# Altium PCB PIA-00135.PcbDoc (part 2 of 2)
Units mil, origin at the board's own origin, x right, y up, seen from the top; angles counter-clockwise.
Board outline 5630 x 2198.54 mil, 6 copper layers (Top Layer, Mid-Layer 1, Mid-Layer 2, Mid-Layer 3, Mid-Layer 4, Bottom Layer), stack 61.94 mil thick; 90 components, 35 nets, 210 pads, 457 vias.
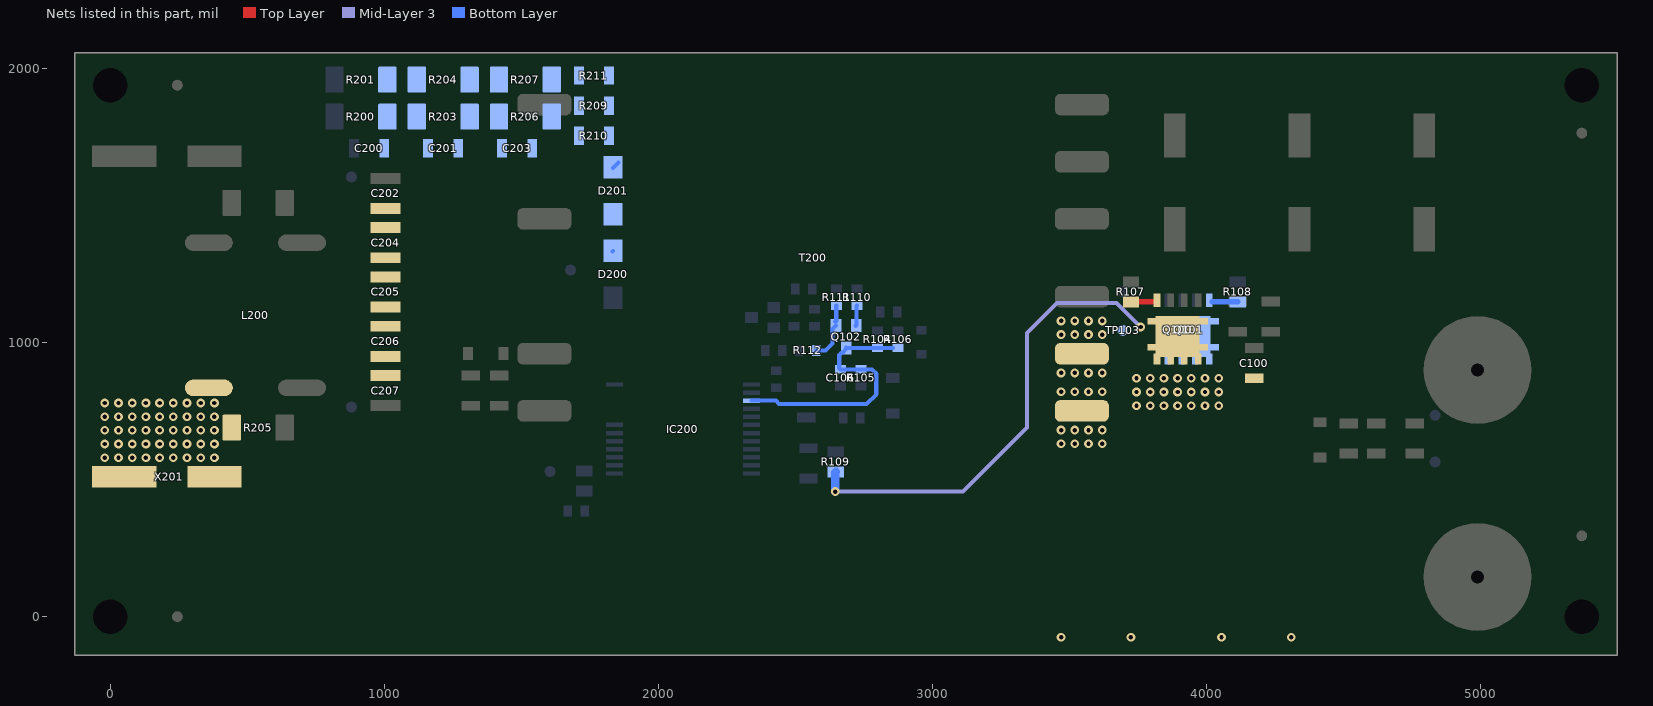
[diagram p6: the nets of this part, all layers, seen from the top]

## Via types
v1: diameter 32, hole 16, Top Layer to Bottom Layer, tented both sides, 409 vias
v2: diameter 32, hole 16, Top Layer to Bottom Layer, tented bottom, 48 vias

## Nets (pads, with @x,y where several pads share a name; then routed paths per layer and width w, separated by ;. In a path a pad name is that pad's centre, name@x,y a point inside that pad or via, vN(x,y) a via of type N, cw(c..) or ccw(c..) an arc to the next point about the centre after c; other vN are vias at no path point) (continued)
NetL200_3: L200.3 R205.1 X201.1 X201.2
  other v1: -20,580.08 30,580.08 80,580.08 130,580.08 180,580.08 230,580.08 280,580.08 330,580.08 380,580.08 -20,630.08 30,630.08 80,630.08 130,630.08 180,630.08 230,630.08 280,630.08 330,630.08 380,630.08 -20,680.08 30,680.08 80,680.08 130,680.08 180,680.08 230,680.08 280,680.08 330,680.08 380,680.08 -20,730.08 30,730.08 80,730.08 130,730.08 180,730.08 230,730.08 280,730.08 330,730.08 380,730.08 -20,780.08 30,780.08 80,780.08 130,780.08 180,780.08 230,780.08 280,780.08 330,780.08 380,780.08
NetQ100_G: Q100.G R107.1 | length 99.9
  Top Layer w20: R107.1@3725,1149 3817.99,1149 3820,1151 Q100.G@3820,1155.11
NetQ101_G: Q101.G R108.1 | length 93
  Bottom Layer w20: 4022,1149 R108.1@4115,1149
NetQ102_B: Q102.B R111.2 R112.1 | length 203
  Bottom Layer w15: R112.1@2576.5,971.69 2610.5,971.69 2636.41,997.6 2636.41,1050.6 Q102.B@2648.5,1062.69 ; Q102.B@2645.5,1076.69 2647.5,1076.69 2649.5,1078.69 2649.5,1134.69 R111.2@2650.5,1135.69
NetQ102_E: Q102.E R110.2 | length 76.1
  Bottom Layer w15: Q102.E@2720.5,1061.69 2724,1065.19 2724,1134.19 R110.2@2725.5,1135.69
SR-K: C100.1 Q100.D Q101.D R109.1 T200.7 T200.8 TP103.1 | length 1711.2
  Mid-Layer 3 w15: v1(2645.5,456.69) 3111.69,456.69 3345,690 3345,1035 3455,1145 3672.15,1145 v1(3760,1057.15)
  Bottom Layer w30: v1(2645.5,456.69) 2645.5,526.05 R109.1@2648.14,528.69
  other v1: 3470,-75 3724.6,-75 4055.39,-75 4310,-75 3470,630.94 3520,630.94 3570,630.94 3620,630.94 3470,680.94 3520,680.94 3570,680.94 3620,680.94 3745,770 3795,770 3845,770 3895,770 3945,770 3995,770 4045,770 3745,820 3795,820 3845,820 3895,820 3945,820 3995,820 4045,820 3470,820.94 3520,820.94 3570,820.94 3620,820.94 3745,870 3795,870 3845,870 3895,870 3945,870 3995,870 4045,870 3470,889.6 3520,889.6 3570,889.6 3620,889.6 3470,1029.6 3520,1029.6 3570,1029.6 3620,1029.6 3470,1079.6 3520,1079.6 3570,1079.6 3620,1079.6
Vbus1: C206.2 C207.1
Vbus2: C205.2 C206.1
Vbus3: C204.2 C205.1
Vbus4: C202.2 C204.1
VFB: C106.2 IC200.3 Q102.C R104.1 R105.2 R106.1 | length 938.1
  Bottom Layer w15: IC200.3@2340.5,788.34 2428.84,788.34 2440.5,776.69 2760.5,776.69 2795.5,811.69 2795.5,886.69 2780.5,901.69 R105.2@2745.5,901.69 ; C106.2@2660.5,906.69 2660.5,955.69 2669.5,964.69 2673.5,964.69 2685.5,976.69 Q102.C@2685.5,980.69 ; C106.2@2665.5,902.69 2739.5,902.69 R105.2@2740.5,901.69 ; Q102.C@2685.5,981.69 2686.5,980.69 R104.1@2800.5,980.69 R106.1@2855.5,980.69
Vsnub1: C200.2 C201.1 R200.2 R201.2 R203.1 R204.1
Vsnub2: C201.2 C203.1 R203.2 R204.2 R206.1 R207.1
Vsnub3: C203.2 R206.2 R207.2 R209.1 R210.1 R211.1
Vsnub4: D201.K R209.2 R210.2 R211.2 | length 28.3
  Bottom Layer w15: D201.K@1835,1637 D201.K@1855,1657
Vsnub5: D200.K D201.A | length 2.9
  Bottom Layer w15: D200.K@1832.96,1333 D200.K@1835,1335.04
pads on no net: HOLE1.0 HOLE2.0 HOLE3.0 HOLE4.0 IC200.8 IC200.9 IC200.10 IC200.11 IC200.12 IC200.15 PM1.0 PM2.0 PM3.0 PM4.0 PM5.0 PM6.0 PM7.0 PM8.0 TP100.2 TP103.2 TP104.2 TP105.2 TP200.2 TP201.2 TP202.2 TP203.2

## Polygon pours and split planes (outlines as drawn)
NetL200_3 on Top Layer "NETL200_3_L01_P449" (solid, remove dead copper, pour order 449): -60,455.08 465,455.08 480,470.08 480,855.08 465,870.08 -60,870.08 -75,855.08 -75,470.08
NetL200_2 on Top Layer "NETL200_2_L01_P448" (solid, remove dead copper, pour order 448): -60,1745 465,1745 480,1730 480,1345 465,1330 -60,1330 -75,1345 -75,1730
"13.5 V (RTN)" on Top Layer "NONET_L01_P-001" (solid, pour order 382): 4700,-100 4385,-100 4370,-85 4370,600 4385,615 4700,615 5190,615 5205,600 5205,-85 5190,-100
NetC100_2 on Top Layer "NETC100_2_L01_P001" (solid, pour order 1): 4285,1015 4285,1095 4275,1105 4075,1105 4065,1095 4065,1015 4120,960 4230,960
SR-K on Top Layer "NONET_L01_P-001" (solid, pour order 441): 3445,1095 3455,1105 4040,1105 4050,1095 4050,1010 4115,945 4235,945 4300,1010 4300,1095 4310,1105 4335,1105 4345,1095 4345,-85 4330,-100 3460,-100 3445,-85
NetC102_2 on Top Layer "NETC102_2_L01_P104" (solid, pour order 104): 4665,700 4650,685 4385,685 4370,700 4370,1100 4345,1125 3855,1125 3845,1135 3845,1190 3840,1195 3825,1195 3820,1200 3820,1245 3810,1255 3685,1255 3675,1245 3675,1135 3665,1125 3454.93,1125 3444.83,1135.1 3444.83,1484.81 3455.02,1495 4845,1495 4885,1455 4885,1255 4885,1140 4665,920
IC200A_D on Top Layer "NONET_L01_P-001" (solid, pour order 428): 1670,1350 1682.73,1362.73 1682.73,1479.57 1671.2,1491.1 1440,1491.1 1430,1481.1 1430,1480 1430,1365 1445,1350
"HV+ (900 V)" on Top Layer "NONET_L01_P-001" (solid, pour order 421): 610,1330 785,1330 800,1345 800,1490 890,1580 1054.14,1580 1095,1620.85 1095,1655 1110,1670 1585,1670 1682.73,1767.73 1682.73,1987.27 1660,2010 675,2010 600,1935 600,1340
"13.5 V (+)" on Top Layer "Top Layer-13.5 V (+)" (solid, pour order 163): 5190,685 5205,700 5205,2000 5190,2015 3455,2015 3445,2005 3445,1525 3455,1515 4860,1515 4905,1470 4905,1125 4685,905 4685,700 4700,685
"HV RTN" on Top Layer "HV_RTN_L01_P381" (solid, pour order 381): 615,870 800,870 880,790 950,790 1220,790 1230,780 1230,710 1240,700 1780,700 1871.1,608.9 1871.1,589.73 1871.1,589.72 1871.1,-88.9 1860,-100 675,-100 600,-25.01 600,855
Vbus3 on Top Layer "VBUS3_L01_P012" (solid, pour order 12): 1060,1310 1060,1240 950,1240 950,1310
Vbus4 on Top Layer "VBUS4_L01_P011" (solid, pour order 11): 1060,1490 1060,1420 950,1420 950,1490
Vbus2 on Top Layer "VBUS2_L01_P013" (solid, pour order 13): 1060,1130 1060,1060 950,1060 950,1130
Vbus1 on Top Layer "VBUS1_L01_P014" (solid, pour order 14): 1060,950 1060,880 950,880 950,950
NetL200_3 on Bottom Layer "NETL200_3_L06_P459" (solid, remove dead copper, pour order 459): -60,455.08 465,455.08 480,470.08 480,855.08 465,870.08 -60,870.08 -75,855.08 -75,470.08
NetL200_2 on Bottom Layer "NETL200_2_L06_P458" (solid, remove dead copper, pour order 458): -60,1745 465,1745 480,1730 480,1345 465,1330 -60,1330 -75,1345 -75,1730
"13.5 V (RTN)" on Bottom Layer "NONET_L01_P-001" (solid, pour order 443): 4700,-100 4385,-100 4370,-85 4370,600 4385,615 4700,615 5190,615 5205,600 5205,-85 5190,-100
SR-K on Bottom Layer "NONET_L01_P-001" (solid, pour order 442): 3445,1095 3455,1105 4040,1105 4050,1095 4050,1010 4115,945 4235,945 4300,1010 4300,1095 4310,1105 4335,1105 4345,1095 4345,-85 4330,-100 3460,-100 3445,-85
NetC102_2 on Bottom Layer "NETC102_2_L06_P383" (solid, pour order 383): 4665,700 4650,685 4385,685 4370,700 4370,1100 4345,1125 4175,1125 4165,1135 4165,1245 4155,1255 4035,1255 4025,1245 4025,1200 4020,1195 3990,1195 3985,1190 3985,1135 3975,1125 3454.93,1125 3444.83,1135.1 3444.83,1484.81 3455.02,1495 4845,1495 4885,1455 4885,1255 4885,1140 4665,920
NetC100_2 on Bottom Layer "NETC100_2_L06_P437" (solid, pour order 437): 4285,1015 4285,1095 4275,1105 4075,1105 4065,1095 4065,1015 4120,960 4230,960
"13.5 V (+)" on Bottom Layer "Top Layer-13.5 V (+)" (solid, pour order 404): 5190,685 5205,700 5205,2000 5190,2015 3455,2015 3445,2005 3445,1525 3455,1515 4860,1515 4905,1470 4905,1125 4685,905 4685,700 4700,685
Vsnub4 on Bottom Layer "NONET_L01_P-001" (solid, pour order 370): 1802,2010 1870,2010 1870,1718.5 1870,1600 1800,1600 1800,1682 1800,1693.91 1802,1695.91
"HV+ (900 V)" on Bottom Layer "NONET_L01_P-001" (solid, pour order 375): 600,1935 600,1340 610,1330 785,1330 800,1345 800,1490 890,1580 908,1598 908,1743.5 872,1743.5 852,1763.49 852,2005.28 847.29,2010 675,2010
Vsnub1 on Bottom Layer "NONET_L01_P-001" (solid, pour order 374): 1178,1675 1173,1670 987,1670 982,1675 982,1743.5 977.99,1747.5 977.99,2005.28 982.7,2010 1147.29,2010 1152,2005.28 1152,1769.49 1178,1743.5
Vsnub2 on Bottom Layer "NONET_L01_P-001" (solid, pour order 373): 1252,1675 1257,1670 1443,1670 1448,1675 1448,1743.5 1452,1747.5 1452,2005.28 1447.29,2010 1282.7,2010 1277.99,2005.28 1277.99,1769.49 1252,1743.5
Vsnub3 on Bottom Layer "NONET_L01_P-001" (solid, pour order 371): 1728,2010 1582.7,2010 1577.99,2005.28 1577.99,1757.99 1563.5,1743.5 1522,1743.5 1522,1670 1675,1670 1728,1723 1728,1788.5
Vsnub5 on Bottom Layer "NONET_L01_P-001" (solid, pour order 369): 1800,1510 1870,1510 1870,1295 1800,1295
IC200A_D on Bottom Layer "NONET_L01_P-001" (solid, pour order 363): 1870.6,839.33 1808.39,839.33 1808.39,1041.6 1645,1205 1645,1325 1620,1350 1445,1350 1430,1365 1430,1481.1 1440,1491.1 1671.2,1491.1 1730,1432.3 1730,1245 1770,1205 1870.6,1205
"HV RTN" on Bottom Layer "HV_RTN_L06_P146" (solid, pour order 146): 880,790 800,870 615,870 600,855 600,-25 660,-85 675,-100 1860,-100 1871.1,-88.9 1871.1,530.67 1808.39,530.67 1808.39,494.59 1808.39,368.39 1730,290 1650,290 1630,310 1630,445 1686.69,501.69 1756.69,501.69 1770.5,515.5 1770.5,571.69 1798.8,600 1871.1,600 1871.1,711.09 1852.19,730 1732.19,730 1685.5,776.69 1685.5,989.5 1575,1100 1255,1100 1195,1100 1127.5,1032.5 1127.5,827.5 1090,790
NetC102_2 on Bottom Layer "NETC102_2_L06_P159" (solid, remove dead copper, pour order 159): 2500.5,816.69 2500.5,891.69 2510.5,901.69 2610.5,901.69 2620.5,891.69 2620.5,816.69 2610.5,806.69 2510.5,806.69
NetL200_3 on Mid-Layer 1 "NETL200_3_L02_P451" (solid, remove dead copper, pour order 451): -60,455.08 465,455.08 480,470.08 480,855.08 465,870.08 -60,870.08 -75,855.08 -75,470.08
NetL200_2 on Mid-Layer 1 "NETL200_2_L02_P450" (solid, remove dead copper, pour order 450): -60,1745 465,1745 480,1730 480,1345 465,1330 -60,1330 -75,1345 -75,1730
"13.5 V (RTN)" on Mid-Layer 1 "NONET_L01_P-001" (solid, pour order 447): 4700,-100 4385,-100 4370,-85 4370,600 4385,615 4700,615 5190,615 5205,600 5205,-85 5190,-100
SR-K on Mid-Layer 1 "NONET_L01_P-001" (solid, pour order 432): 3445,1095 3455,1105 4040,1105 4050,1095 4050,1010 4115,945 4235,945 4300,1010 4300,1095 4310,1105 4335,1105 4345,1095 4345,-85 4330,-100 3460,-100 3445,-85
NetC100_2 on Mid-Layer 1 "NETC100_2_L02_P433" (solid, pour order 433): 4285,1015 4285,1095 4275,1105 4075,1105 4065,1095 4065,1015 4120,960 4230,960
IC200A_D on Mid-Layer 1 "NONET_L01_P-001" (solid, pour order 424): 1670,1350 1682.73,1362.73 1682.73,1479.57 1671.2,1491.1 1440,1491.1 1430,1481.1 1430,1480 1430,1365 1445,1350
"HV+ (900 V)" on Mid-Layer 1 "NONET_L01_P-001" (solid, pour order 376): 890,1580 800,1490 800,1345 785,1330 610,1330 600,1340 600,1935 675,2010 1660,2010 1682.73,1987.27 1682.73,1767.73 1585,1670 1110,1670 1095,1655 1095,1620.85 1054.14,1580
"HV RTN" on Mid-Layer 1 "HV_RTN_L02_P420" (solid, pour order 420): 880,790 800,870 615,870 600,855 600,-25 660,-85 675,-100 1860,-100 1871.1,-88.9 1871.1,711.09 1852.19,730 1732.19,730 1685.5,776.69 1685.5,989.5 1575,1100 1255,1100 1195,1100 1127.5,1032.5 1127.5,827.5 1090,790
"13.5 V (+)" on Mid-Layer 1 "Top Layer-13.5 V (+)" (solid, pour order 408): 5190,685 5205,700 5205,2000 5190,2015 3455,2015 3445,2005 3445,1525 3455,1515 4860,1515 4905,1470 4905,1125 4685,905 4685,700 4700,685
NetC102_2 on Mid-Layer 1 "NETC102_2_L02_P389" (solid, pour order 389): 4665,700 4650,685 4385,685 4370,700 4370,1100 4345,1125 3454.93,1125 3425,1095.07 3425,415 3410,400 2325,400 2310,415 2310,1480 2325,1495 4845,1495 4885,1455 4885,1255 4885,1140 4665,920
"HV+ (900 V)" on Mid-Layer 3 "NONET_L01_P-001" (solid, pour order 461): 890,1580 800,1490 800,1345 785,1330 610,1330 600,1340 600,1935 675,2010 1660,2010 1682.73,1987.27 1682.73,1767.73 1585,1670 1110,1670 1095,1655 1095,1620.85 1054.14,1580
NetL200_3 on Mid-Layer 3 "NETL200_3_L04_P455" (solid, remove dead copper, pour order 455): -60,455.08 465,455.08 480,470.08 480,855.08 465,870.08 -60,870.08 -75,855.08 -75,470.08
NetL200_2 on Mid-Layer 3 "NETL200_2_L04_P454" (solid, remove dead copper, pour order 454): -60,1745 465,1745 480,1730 480,1345 465,1330 -60,1330 -75,1345 -75,1730
"13.5 V (RTN)" on Mid-Layer 3 "NONET_L01_P-001" (solid, pour order 445): 4700,-100 4385,-100 4370,-85 4370,600 4385,615 4700,615 5190,615 5205,600 5205,-85 5190,-100
SR-K on Mid-Layer 3 "NONET_L01_P-001" (solid, pour order 438): 3445,1095 3455,1105 4040,1105 4050,1095 4050,1010 4115,945 4235,945 4300,1010 4300,1095 4310,1105 4335,1105 4345,1095 4345,-85 4330,-100 3460,-100 3445,-85
NetC100_2 on Mid-Layer 3 "NETC100_2_L04_P435" (solid, pour order 435): 4285,1015 4285,1095 4275,1105 4075,1105 4065,1095 4065,1015 4120,960 4230,960
IC200A_D on Mid-Layer 3 "NONET_L01_P-001" (solid, pour order 429): 1670,1350 1682.73,1362.73 1682.73,1479.57 1671.2,1491.1 1440,1491.1 1430,1481.1 1430,1480 1430,1365 1445,1350
"HV RTN" on Mid-Layer 3 "HV_RTN_L04_P418" (solid, pour order 418): 880,790 800,870 615,870 600,855 600,-25 660,-85 675,-100 1860,-100 1871.1,-88.9 1871.1,711.09 1852.19,730 1732.19,730 1685.5,776.69 1685.5,989.5 1575,1100 1255,1100 1195,1100 1127.5,1032.5 1127.5,827.5 1090,790
"13.5 V (+)" on Mid-Layer 3 "Top Layer-13.5 V (+)" (solid, pour order 406): 5190,685 5205,700 5205,2000 5190,2015 3455,2015 3445,2005 3445,1525 3455,1515 4860,1515 4905,1470 4905,1125 4685,905 4685,700 4700,685
NetC102_2 on Mid-Layer 3 "NETC102_2_L04_P386" (solid, pour order 386): 4665,700 4650,685 4385,685 4370,700 4370,1100 4345,1125 3454.93,1125 3425,1095.07 3425,415 3410,400 2325,400 2310,415 2310,1480 2325,1495 4845,1495 4885,1455 4885,1255 4885,1140 4665,920
"HV+ (900 V)" on Mid-Layer 2 "NONET_L01_P-001" (solid, pour order 460): 890,1580 800,1490 800,1345 785,1330 610,1330 600,1340 600,1935 675,2010 1660,2010 1682.73,1987.27 1682.73,1767.73 1585,1670 1110,1670 1095,1655 1095,1620.85 1054.14,1580
NetL200_3 on Mid-Layer 2 "NETL200_3_L03_P453" (solid, remove dead copper, pour order 453): -60,455.08 465,455.08 480,470.08 480,855.08 465,870.08 -60,870.08 -75,855.08 -75,470.08
NetL200_2 on Mid-Layer 2 "NETL200_2_L03_P452" (solid, remove dead copper, pour order 452): -60,1745 465,1745 480,1730 480,1345 465,1330 -60,1330 -75,1345 -75,1730
"13.5 V (RTN)" on Mid-Layer 2 "NONET_L01_P-001" (solid, pour order 446): 4700,-100 4385,-100 4370,-85 4370,600 4385,615 4700,615 5190,615 5205,600 5205,-85 5190,-100
SR-K on Mid-Layer 2 "NONET_L01_P-001" (solid, pour order 439): 3445,1095 3455,1105 4040,1105 4050,1095 4050,1010 4115,945 4235,945 4300,1010 4300,1095 4310,1105 4335,1105 4345,1095 4345,-85 4330,-100 3460,-100 3445,-85
NetC100_2 on Mid-Layer 2 "NETC100_2_L03_P434" (solid, pour order 434): 4285,1015 4285,1095 4275,1105 4075,1105 4065,1095 4065,1015 4120,960 4230,960
IC200A_D on Mid-Layer 2 "NONET_L01_P-001" (solid, pour order 366): 1670,1350 1682.73,1362.73 1682.73,1479.57 1671.2,1491.1 1440,1491.1 1430,1481.1 1430,1480 1430,1365 1445,1350
"HV RTN" on Mid-Layer 2 "HV_RTN_L03_P419" (solid, pour order 419): 880,790 800,870 615,870 600,855 600,-25 660,-85 675,-100 1860,-100 1871.1,-88.9 1871.1,711.09 1852.19,730 1732.19,730 1685.5,776.69 1685.5,989.5 1575,1100 1255,1100 1195,1100 1127.5,1032.5 1127.5,827.5 1090,790
"13.5 V (+)" on Mid-Layer 2 "Top Layer-13.5 V (+)" (solid, pour order 407): 5190,685 5205,700 5205,2000 5190,2015 3455,2015 3445,2005 3445,1525 3455,1515 4860,1515 4905,1470 4905,1125 4685,905 4685,700 4700,685
NetC102_2 on Mid-Layer 2 "NETC102_2_L03_P388" (solid, pour order 388): 4665,700 4650,685 4385,685 4370,700 4370,1100 4345,1125 3454.93,1125 3425,1095.07 3425,415 3410,400 2325,400 2310,415 2310,1480 2325,1495 4845,1495 4885,1455 4885,1255 4885,1140 4665,920
NetL200_3 on Mid-Layer 4 "NETL200_3_L05_P457" (solid, remove dead copper, pour order 457): -60,455.08 465,455.08 480,470.08 480,855.08 465,870.08 -60,870.08 -75,855.08 -75,470.08
NetL200_2 on Mid-Layer 4 "NETL200_2_L05_P456" (solid, remove dead copper, pour order 456): -60,1745 465,1745 480,1730 480,1345 465,1330 -60,1330 -75,1345 -75,1730
"13.5 V (RTN)" on Mid-Layer 4 "NONET_L01_P-001" (solid, pour order 444): 4700,-100 4385,-100 4370,-85 4370,600 4385,615 4700,615 5190,615 5205,600 5205,-85 5190,-100
SR-K on Mid-Layer 4 "NONET_L01_P-001" (solid, pour order 440): 3445,1095 3455,1105 4040,1105 4050,1095 4050,1010 4115,945 4235,945 4300,1010 4300,1095 4310,1105 4335,1105 4345,1095 4345,-85 4330,-100 3460,-100 3445,-85
NetC100_2 on Mid-Layer 4 "NETC100_2_L05_P436" (solid, pour order 436): 4285,1015.08 4285,1095 4275,1105 4074.91,1105 4065.25,1095.34 4065.25,1015.34 4120.25,960.34 4230.25,960.34
IC200A_D on Mid-Layer 4 "NONET_L01_P-001" (solid, pour order 430): 1670,1350 1682.73,1362.73 1682.73,1479.57 1671.2,1491.1 1440,1491.1 1430,1481.1 1430,1480 1430,1365 1445,1350
"HV RTN" on Mid-Layer 4 "HV_RTN_L05_P417" (solid, pour order 417): 880,790 800,870 615,870 600,855 600,-25 660,-85 675,-100 1860,-100 1871.1,-88.9 1871.1,711.09 1852.19,730 1732.19,730 1685.5,776.69 1685.5,989.5 1575,1100 1255,1100 1195,1100 1127.5,1032.5 1127.5,827.5 1090,790
"13.5 V (+)" on Mid-Layer 4 "Top Layer-13.5 V (+)" (solid, pour order 405): 5190,685 5205,700 5205,2000 5190,2015 3455,2015 3445,2005 3445,1525 3455,1515 4860,1515 4905,1470 4905,1125 4685,905 4685,700 4700,685
NetC102_2 on Mid-Layer 4 "NETC102_2_L05_P387" (solid, pour order 387): 4665,700 4650,685 4385,685 4370,700 4370,1100 4345,1125 3454.93,1125 3425,1095.07 3425,415 3410,400 2325,400 2310,415 2310,1480 2325,1495 4845,1495 4885,1455 4885,1255 4885,1140 4665,920

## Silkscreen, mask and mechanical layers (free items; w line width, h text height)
Top Overlay:
  drawing of 30 lines, arcs and shapes, not listed
  text "VIN (+)" at 115,1816.69 h100
  text "900V" at -15,960 h118.11
  text "⊕" at 4600,783.52 h400
  text "13.5V / 6.37A" at 4695,473.08 h100
  text "86W" at 4865,386.27 h100
  text "VIN (-)" at 115,316.69 h100
  text "'.ProductNamePCB'" at 880,205 h118.11
  text "HV" at 1704.68,134.68 h78.74
  text "LV" at 2329.68,134.68 h78.74
  text "'.PCBNumber'" at 910,120 h100
  text "⊖" at 4600,38.52 h400
Bottom Solder:
  lines w10: 2809.41,83.78 2809.41,44.41 2848.78,44.41 ; 2809.41,280.63 2809.41,320 2848.78,320 ; 3175.63,44.41 3215,44.41 3215,83.78 ; 3175.63,320 3215,320 3215,280.63
Remark:
  text "Product:" at 599.72,-439.35 h70
  text ".TitleP" at 845,-440 h70
  text ".DATE_PRINT" at 595.09,-565.76 h70
  text ".TIME_PRINT" at 945.09,-565.76 h70
  text ".Pcb_File_Name_No_Path" at 595.09,-665.76 h70
  text ".Printout_Name" at 595.09,-765.76 h70
  text ".PLOT_FILE_NAME" at 595.09,-865.76 h70
  text ".PRINT_SCALE" at 595.09,-965.76 h70
  text "Attention: The wires of THT components must not stand out more than 1.0mm !!" at 595.09,-1065.76 h70
Outline:
  the board outline again, w10
Cutout:
  lines w10: -135,-140 ccw(c-130,-140) -130,-145 ; -135,-140 ccw(c-130,-140) -130,-145 ; -135,-140 -135,2058.54 ; -135,2058.54 cw(c-130,2058.54) -130,2063.54 ; -135,2058.54 cw(c-130,2058.54) -130,2063.54 ; -130,-145 5500,-145 ; -130,2063.54 5500,2063.54 ; 1348.32,1519.55 ccw(c1344.8,1523.11) 1348.34,1519.57 ; 1348.32,1519.55 ccw(c1344.8,1523.11) 1348.34,1519.57 ; 1348.32,1519.55 ccw(c1358.96,1508.96) 1343.94,1508.96 1343.94,1325 ccw(c1358.96,1325) 1373.97,1325 1373.97,1500.67 ; 1348.33,1519.57 ccw(c1358.96,1508.96) 1348.32,1519.55 ; 1348.34,1519.57 ccw(c1358.96,1508.96) 1348.33,1519.57 ; 1348.34,1519.58 ccw(c1358.96,1508.96) 1348.34,1519.57 ; 1348.34,1519.58 cw(c1358.96,1508.96) 1348.37,1519.6 ; 1348.34,1519.58 1348.39,1519.62 ; 1348.34,1519.57 1348.34,1519.58 ; 1348.33,1519.57 1348.34,1519.57 ; 1348.34,1519.57 1348.37,1519.61 ; 1348.37,1519.61 ccw(c1344.84,1523.14) 1348.39,1519.62 ; 1348.37,1519.6 ccw(c1344.84,1523.14) 1348.37,1519.61 ; 1348.37,1519.61 ccw(c1344.84,1523.14) 1348.39,1519.62 ; 1348.39,1519.62 1399.33,1570.56 ; 1360,1175.01 ccw(c1360,1180.01) 1360.04,1175.01 ; 1360,1175.01 ccw(c1360,1160) 1360,1144.98 1596.71,1144.98 ; 1360,1175.01 1360.04,1175.01 ; 1360.04,1175.01 1604.97,1175.01 ; 1373.97,1500.67 cw(c1378.97,1500.67) 1375.45,1504.22 ; 1373.97,1500.67 cw(c1378.97,1500.67) 1375.43,1504.2 ; 1375.45,1504.22 1414.73,1543.5 ; 1375.43,1504.2 1375.45,1504.22 ; 1399.35,1570.59 cw(c1410,1560) 1399.38,1570.61 ; 1399.33,1570.56 ccw(c1395.81,1574.11) 1399.35,1570.58 ; 1399.35,1570.58 ccw(c1395.81,1574.11) 1399.35,1570.59 ; 1399.33,1570.56 ccw(c1395.81,1574.11) 1399.35,1570.58 ; 1399.35,1570.58 1399.38,1570.61 ; 1399.33,1570.56 1399.38,1570.61 ; 1399.38,1570.61 ccw(c1410,1560) 1399.38,1570.61 ; 1399.39,1570.62 ccw(c1410,1560) 1399.38,1570.61 ; 1399.4,1570.63 ccw(c1410,1560) 1399.39,1570.62 ; 1399.4,1570.63 cw(c1410,1560) 1410,1575.01 1710,1575.01 cw(c1710,1560) 1725.01,1560 cw(c1710,1560) 1710,1544.98 1418.29,1544.98 ; 1399.38,1570.61 ccw(c1395.84,1574.15) 1399.4,1570.63 ; 1399.38,1570.61 ccw(c1395.84,1574.15) 1399.4,1570.63 ; 1399.38,1570.61 1399.39,1570.62 ; 1399.38,1570.61 1399.38,1570.61 ; 1414.75,1543.52 cw(c1418.29,1539.98) 1418.29,1544.98 ; 1414.73,1543.5 cw(c1418.29,1539.98) 1418.29,1544.98 ; 1414.73,1543.5 1414.75,1543.52 ; 1596.71,1144.98 cw(c1596.71,1139.98) 1600.26,1143.5 ; 1596.71,1144.98 cw(c1596.71,1139.98) 1600.24,1143.52 1600.26,1143.5 ; 1600.26,1143.5 1728.5,1015.26 ; 1604.96,1175.01 ccw(c1605,1180.01) 1605,1175.01 ; 1605,1175.01 cw(c1605,1160) 1615.61,1170.61 ; 1604.97,1175.01 1605,1175.01 ; 1615.65,1170.58 ccw(c1619.18,1174.11) 1615.66,1170.56 ; 1615.64,1170.59 ccw(c1605,1160) 1615.61,1170.61 ; 1615.65,1170.58 ccw(c1619.18,1174.11) 1615.68,1170.55 ; 1615.64,1170.59 ccw(c1619.18,1174.11) 1615.65,1170.58 ; 1615.65,1170.58 1615.61,1170.61 ; 1615.61,1170.61 ccw(c1619.15,1174.15) 1615.61,1170.61 ; 1615.61,1170.61 ccw(c1619.15,1174.15) 1615.61,1170.61 ; 1615.61,1170.61 ccw(c1605,1160) 1615.61,1170.61 ; 1615.61,1170.61 1615.66,1170.56 ; 1615.66,1170.56 1615.68,1170.55 ; 1615.68,1170.55 1755.55,1030.68 ; 1728.5,1015.26 cw(c1724.98,1011.71) 1729.98,1011.71 ; 1728.5,1015.26 1728.52,1015.24 cw(c1724.98,1011.71) 1729.98,1011.71 ; 1729.98,810 ccw(c1745,810) 1734.36,799.4 ; 1729.98,810 1729.98,1011.71 ; 1729.98,810 1729.98,810 ; 1734.4,799.36 ccw(c1745,810) 1734.41,799.35 ; 1734.38,799.38 ccw(c1745,810) 1734.4,799.36 ; 1734.38,799.38 cw(c1745,810) 1734.36,799.4 ; 1734.41,799.35 cw(c1730.88,795.81) 1734.41,799.35 ; 1734.38,799.38 ccw(c1730.84,795.84) 1734.36,799.4 ; 1734.38,799.38 ccw(c1730.84,795.84) 1734.36,799.4 ; 1734.38,799.38 1734.41,799.35 ; 1734.38,799.38 1734.4,799.36 ; 1734.4,799.36 1734.43,799.33 ; 1734.43,799.33 ccw(c1730.88,795.81) 1734.41,799.35 ; 1734.43,799.33 ccw(c1730.88,795.81) 1734.41,799.35 ; 1734.43,799.33 1764.33,769.43 ; 1755.55,1030.68 ccw(c1759.11,1034.18) 1755.58,1030.65 ; 1755.55,1030.68 1755.56,1030.66 ; 1755.56,1030.66 ccw(c1759.11,1034.18) 1755.58,1030.65 ; 1755.58,1030.65 ccw(c1759.11,1034.18) 1755.59,1030.64 cw(c1745,1020) 1755.61,1030.61 ; 1755.58,1030.65 1755.61,1030.61 ; 1755.56,1030.66 1755.61,1030.61 ; 1755.61,1030.61 ccw(c1759.15,1034.15) 1755.61,1030.61 ; 1755.61,1030.61 ccw(c1759.15,1034.15) 1755.61,1030.61 ; 1755.61,1030.61 ccw(c1745,1020) 1755.61,1030.61 ; 1755.61,1030.61 cw(c1745,1020) 1760.01,1020 ; 1760.01,818.29 ccw(c1765.01,818.29) 1761.49,814.73 ; 1760.01,818.29 ccw(c1765.01,818.29) 1761.48,814.75 1761.49,814.73 ; 1760.01,818.29 1760.01,1019.97 ; 1760.01,1019.96 cw(c1765.01,1020) 1760.01,1020 ; 1760.01,1019.97 1760.01,1020 ; 1760.01,1020 ccw(c1745,1020) 1760.01,1020 ; 1761.49,814.73 1779.73,796.49 ; 1764.35,769.41 ccw(c1760.81,765.88) 1764.33,769.43 ; 1764.35,769.41 ccw(c1760.81,765.88) 1764.35,769.41 ; 1764.35,769.41 ccw(c1760.81,765.88) 1764.33,769.43 ; 1764.35,769.41 ccw(c1775,780) 1764.36,769.4 ; 1764.33,769.43 1764.36,769.4 ; 1764.35,769.41 1764.38,769.38 ; 1764.4,769.36 ccw(c1775,780) 1775,764.98 ; 1764.38,769.38 ccw(c1775,780) 1764.4,769.36 ; 1764.38,769.38 cw(c1775,780) 1764.36,769.4 ; 1764.4,769.36 ccw(c1760.84,765.84) 1764.38,769.38 ; 1764.4,769.36 ccw(c1760.84,765.84) 1764.38,769.38 ; 1764.38,769.38 1764.36,769.4 ; 1775,764.98 ccw(c1775,780) 1775,764.98 ; 1775,764.98 ccw(c1775,759.98) 1775,764.98 ; 1775,764.98 ccw(c1775,759.98) 1775,764.98 ; 1775,764.98 1925,764.98 ; 1775,764.98 1775,764.98 ; 1779.73,796.49 ccw(c1783.29,800.01) 1783.29,795.01 ; 1779.73,796.49 1779.75,796.48 ccw(c1783.29,800.01) 1783.29,795.01 ; 1783.29,795.01 1924.97,795.01 ; 1925,764.98 ccw(c1925,780) 1940.01,780 ; 1925,764.98 ccw(c1925,780) 1925,764.98 ; 1925,764.98 ccw(c1925,759.98) 1925,764.98 ; 1925,764.98 ccw(c1925,759.98) 1925,764.98 ; 1925,764.98 1925,764.98 ; 1925,764.98 1925,764.98 ; 1924.96,795.01 ccw(c1925,800.01) 1925,795.01 ; 1925,795.01 cw(c1925,780) 1940.01,780 ; 1924.97,795.01 1925,795.01 ; 1940.01,780 ccw(c1945.01,780) 1940.01,780 ; 1940.01,780 ccw(c1945.01,780) 1940.01,780 ; 1940.01,780 ccw(c1945.01,780) 1940.01,780 ; 1940.01,780 ccw(c1925,780) 1940.01,780 ; 1940.01,780 ccw(c1925,780) 1940.01,780 ; 5500,-145 ccw(c5500,-140) 5505,-140 ; 5500,-145 ccw(c5500,-140) 5505,-140 ; 5500,2063.54 cw(c5500,2058.54) 5505,2058.54 ; 5500,2063.54 cw(c5500,2058.54) 5505,2058.54 ; 5505,-140 5505,2058.54
  text "PCB contour and milled cutout" at 4440,3090 h70
Dimension:
  the board outline again, w10
Top WEB:
  text ".Print_Date" at 690.09,2614.24 h70
Bot WEB:
  lines w10: 1930.47,284.97 1933.79,1072.36 2721.19,1075.69 2717.87,288.29 1930.47,284.97
Route Tool Path:
  lines w31.5: -145.75,-140 ccw(c-130,-140) -130,-155.75 ; -145.75,-140 ccw(c-130,-140) -130,-155.75 ; -145.75,-140 -145.75,2058.54 ; -145.75,2058.54 cw(c-130,2058.54) -130,2074.29 ; -145.75,2058.54 cw(c-130,2058.54) -130,2074.29 ; -130,-155.75 5500,-155.75 ; -130,2074.29 5500,2074.29 ; 1355.92,1511.95 ccw(c1344.8,1523.11) 1355.94,1511.97 ; 1355.95,1511.98 ccw(c1344.84,1523.14) 1355.97,1512.01 ; 1355.95,1511.98 ccw(c1344.84,1523.14) 1355.95,1511.98 ; 1355.92,1511.95 ccw(c1358.96,1508.96) 1354.69,1508.96 1354.69,1325 ccw(c1358.96,1325) 1363.22,1325 1363.22,1500.67 ; 1355.94,1511.97 ccw(c1358.96,1508.96) 1355.92,1511.95 ; 1355.95,1511.98 ccw(c1358.96,1508.96) 1355.94,1511.97 ; 1355.92,1511.95 ccw(c1344.8,1523.11) 1355.94,1511.97 ; 1355.95,1511.98 1356,1512.03 ; 1355.94,1511.97 1355.95,1511.98 ; 1355.94,1511.97 1355.97,1512.01 ; 1355.97,1512.01 ccw(c1344.84,1523.14) 1356,1512.03 ; 1355.97,1512.01 ccw(c1344.84,1523.14) 1356,1512.03 ; 1356,1512.03 1406.92,1562.96 ; 1360,1164.26 ccw(c1360,1180.01) 1360.08,1164.26 ; 1360,1164.26 ccw(c1360,1160) 1360,1155.73 1596.71,1155.73 ; 1360,1164.26 1360.08,1164.26 ; 1360.08,1164.26 1604.94,1164.26 ; 1363.22,1500.67 cw(c1378.97,1500.67) 1367.86,1511.83 ; 1363.22,1500.67 cw(c1378.97,1500.67) 1367.83,1511.8 ; 1367.86,1511.83 1407.13,1551.09 ; 1367.83,1511.8 1367.86,1511.83 ; 1406.95,1562.98 ccw(c1395.81,1574.11) 1406.97,1563 ; 1406.92,1562.96 ccw(c1395.81,1574.11) 1406.95,1562.98 ; 1406.92,1562.96 ccw(c1395.81,1574.11) 1406.95,1562.98 ; 1406.92,1562.96 1406.97,1563 ; 1406.95,1562.98 1406.98,1563.01 ; 1406.98,1563.01 ccw(c1395.84,1574.15) 1407,1563.03 ; 1406.98,1563.01 ccw(c1395.84,1574.15) 1407,1563.03 ; 1406.98,1563.01 ccw(c1410,1560) 1406.97,1563.01 ; 1407,1563.03 ccw(c1410,1560) 1406.98,1563.01 ; 1407,1563.03 cw(c1410,1560) 1410,1564.26 1710,1564.26 cw(c1710,1560) 1714.26,1560 cw(c1710,1560) 1710,1555.73 1418.29,1555.73 ; 1406.97,1563 ccw(c1395.81,1574.11) 1406.97,1563.01 ; 1406.97,1563 1406.98,1563.01 ; 1407.15,1551.12 cw(c1418.29,1539.98) 1418.29,1555.73 ; 1407.13,1551.09 cw(c1418.29,1539.98) 1418.29,1555.73 ; 1407.13,1551.09 1407.15,1551.12 ; 1596.71,1155.73 cw(c1596.71,1139.98) 1607.87,1151.09 ; 1596.71,1155.73 cw(c1596.71,1139.98) 1607.84,1151.12 1607.87,1151.09 ; 1604.94,1164.26 ccw(c1605,1180.01) 1605,1164.26 ; 1604.94,1164.26 1605,1164.26 ; 1605,1164.26 cw(c1605,1160) 1608.01,1163.01 ; 1607.87,1151.09 1736.09,1022.87 ; 1608.05,1162.98 ccw(c1619.18,1174.11) 1608.07,1162.96 ; 1608.05,1162.98 ccw(c1619.18,1174.11) 1608.1,1162.93 ; 1608.05,1162.98 cw(c1619.18,1174.11) 1608.02,1163.01 ; 1608.05,1162.98 1608.01,1163.01 ; 1608.01,1163.01 ccw(c1619.15,1174.15) 1608.01,1163.01 ; 1608.01,1163.01 ccw(c1619.15,1174.15) 1608.01,1163.01 ; 1608.01,1163.01 ccw(c1605,1160) 1608.01,1163.01 ; 1608.02,1163.01 ccw(c1605,1160) 1608.01,1163.01 ; 1608.01,1163.01 1608.07,1162.96 ; 1608.1,1162.93 1608.07,1162.96 ; 1608.1,1162.93 1747.93,1023.1 ; 1736.09,1022.87 cw(c1724.98,1011.71) 1740.73,1011.71 ; 1736.09,1022.87 1736.12,1022.84 cw(c1724.98,1011.71) 1740.73,1011.71 ; 1740.73,810 ccw(c1745,810) 1741.96,807 ; 1740.73,810 1740.73,1011.71 ; 1740.73,810 1740.73,810 ; 1741.98,806.98 ccw(c1745,810) 1741.99,806.97 ; 1741.98,806.98 cw(c1745,810) 1741.96,807 ; 1741.99,806.97 ccw(c1730.88,795.81) 1741.99,806.97 ; 1741.99,806.97 cw(c1730.88,795.81) 1742.01,806.95 ; 1741.98,806.98 ccw(c1730.84,795.84) 1741.96,807 ; 1741.98,806.98 ccw(c1730.84,795.84) 1741.96,807 ; 1741.98,806.98 1742.01,806.95 ; 1741.98,806.98 1741.99,806.97 ; 1741.99,806.97 1742.04,806.92 ; 1742.04,806.92 ccw(c1730.88,795.81) 1742.01,806.95 ; 1742.04,806.92 ccw(c1730.88,795.81) 1742.01,806.95 ; 1742.04,806.92 1771.92,777.04 ; 1747.96,1023.07 ccw(c1759.11,1034.18) 1747.98,1023.05 ; 1747.96,1023.07 1747.93,1023.1 ; 1747.96,1023.07 1748.01,1023.01 ; 1747.93,1023.1 ccw(c1759.11,1034.18) 1747.98,1023.05 ; 1747.98,1023.05 ccw(c1759.11,1034.18) 1748.01,1023.02 cw(c1745,1020) 1748.01,1023.01 ; 1747.98,1023.05 1748.01,1023.01 ; 1748.01,1023.01 ccw(c1759.15,1034.15) 1748.01,1023.01 ; 1748.01,1023.01 ccw(c1759.15,1034.15) 1748.01,1023.01 ; 1748.01,1023.01 ccw(c1745,1020) 1748.01,1023.01 ; 1748.01,1023.01 cw(c1745,1020) 1749.26,1020 ; 1749.26,818.29 ccw(c1765.01,818.29) 1753.88,807.15 1753.9,807.13 ; 1749.26,818.29 ccw(c1765.01,818.29) 1753.9,807.13 ; 1749.26,818.29 1749.26,1019.94 ; 1749.26,1019.94 cw(c1765.01,1020) 1749.26,1020 ; 1749.26,1019.94 1749.26,1020 ; 1749.26,1020 ccw(c1745,1020) 1749.26,1020 ; 1753.9,807.13 1772.13,788.9 ; 1771.95,777.01 ccw(c1760.81,765.88) 1771.92,777.04 ; 1771.95,777.01 cw(c1760.81,765.88) 1771.97,776.99 ; 1771.95,777.01 ccw(c1760.81,765.88) 1771.92,777.04 ; 1771.92,777.04 1771.97,776.99 ; 1771.95,777.01 1771.98,776.98 ; 1771.97,776.99 ccw(c1760.81,765.88) 1771.97,776.99 ; 1772,776.96 ccw(c1775,780) 1775,775.73 ; 1771.98,776.98 ccw(c1775,780) 1772,776.96 ; 1771.97,776.99 ccw(c1775,780) 1771.98,776.98 ; 1772,776.96 ccw(c1760.84,765.84) 1771.98,776.98 ; 1772,776.96 ccw(c1760.84,765.84) 1771.98,776.98 ; 1771.98,776.98 1771.97,776.99 ; 1772.13,788.9 ccw(c1783.29,800.01) 1783.29,784.26 ; 1772.13,788.9 1772.15,788.88 ccw(c1783.29,800.01) 1783.29,784.26 ; 1775,775.73 ccw(c1775,780) 1775,775.73 ; 1775,775.73 ccw(c1775,759.98) 1775,775.73 ; 1775,775.73 ccw(c1775,759.98) 1775,775.73 ; 1775,775.73 1925,775.73 ; 1775,775.73 1775,775.73 ; 1783.29,784.26 1924.94,784.26 ; 1924.94,784.26 ccw(c1925,800.01) 1925,784.26 ; 1924.94,784.26 1925,784.26 ; 1925,775.73 ccw(c1925,780) 1929.26,780 ; 1925,775.73 ccw(c1925,780) 1925,775.73 ; 1925,775.73 ccw(c1925,759.98) 1925,775.73 ; 1925,775.73 ccw(c1925,759.98) 1925,775.73 ; 1925,775.73 1925,775.73 ; 1925,775.73 1925,775.73 ; 1925,784.26 cw(c1925,780) 1929.26,780 ; 1929.26,780 ccw(c1945.01,780) 1929.26,780 ; 1929.26,780 ccw(c1945.01,780) 1929.26,780 ; 1929.26,780 ccw(c1925,780) 1929.26,780 ; 1929.26,780 ccw(c1945.01,780) 1929.26,780 ; 1929.26,780 ccw(c1945.01,780) 1929.26,780 ; 1929.26,780 ccw(c1925,780) 1929.26,780 ; 5500,-155.75 ccw(c5500,-140) 5515.75,-140 ; 5500,-155.75 ccw(c5500,-140) 5515.75,-140 ; 5500,2074.29 cw(c5500,2058.54) 5515.75,2058.54 ; 5500,2074.29 cw(c5500,2058.54) 5515.75,2058.54 ; 5515.75,-140 5515.75,2058.54
Drill Drawing:
  circle w10: c6377.58,3254.97 r26.65
  lines w10: 6350.93,3121.72 6364.25,3121.72 6364.25,3108.4 6390.9,3108.4 6390.9,3121.72 6404.23,3121.72 6404.23,3148.37 6390.9,3148.37 6390.9,3161.7 6364.25,3161.7 6364.25,3148.37 6350.93,3148.37 6350.93,3121.72 ; 6350.93,3348.25 6404.23,3348.25 6404.23,3401.55 6350.93,3401.55 6350.93,3348.25
  lines w15: 436.52,2483.18 827.45,2483.18 1712.92,2483.18 2531.81,2483.18 3322.17,2483.18 ; 436.52,2597.34 827.45,2597.34 1712.92,2597.34 2531.81,2597.34 3322.17,2597.34 ; 436.52,2711.5 827.45,2711.5 1712.92,2711.5 2531.81,2711.5 3322.17,2711.5 ; 436.52,2825.66 827.45,2825.66 1712.92,2825.66 2531.81,2825.66 3322.17,2825.66 ; 436.52,2939.82 827.45,2939.82 1712.92,2939.82 2531.81,2939.82 3322.17,2939.82 ; 436.52,3053.98 827.45,3053.98 1712.92,3053.98 2531.81,3053.98 3322.17,3053.98 ; 436.52,3168.14 827.45,3168.14 1712.92,3168.14 2531.81,3168.14 3322.17,3168.14 ; 436.52,3282.3 827.45,3282.3 1712.92,3282.3 2531.81,3282.3 3322.17,3282.3 ; 436.52,3396.46 827.45,3396.46 1712.92,3396.46 2531.81,3396.46 3322.17,3396.46 ; 436.52,3510.62 827.45,3510.62 1712.92,3510.62 2531.81,3510.62 3322.17,3510.62 ; 436.52,3624.78 827.45,3624.78 1712.92,3624.78 2531.81,3624.78 3322.17,3624.78 ; 436.52,3738.93 827.45,3738.93 1712.92,3738.93 2531.81,3738.93 3322.17,3738.93 ; 436.52,3853.09 827.45,3853.09 1712.92,3853.09 2531.81,3853.09 3322.17,3853.09 ; 436.52,3967.25 827.45,3967.25 1712.92,3967.25 2531.81,3967.25 3322.17,3967.25 ; 436.52,4081.41 3322.17,4081.41 ; 827.45,4195.57 827.45,2369.02 ; 1712.92,4195.57 1712.92,2369.02 ; 2531.81,4195.57 2531.81,2369.02 ; 6302.5,3072.42 8967.8,3072.42 ; 6302.5,3432.2 8967.8,3432.2 ; 6596.02,2952.5 6596.02,3552.12 ; 6870.21,2952.5 6870.21,3552.12 ; 7409.11,2952.5 7409.11,3552.12 ; 7634.74,2952.5 7634.74,3552.12 ; 7965.61,2952.5 7965.61,3552.12 ; 8346.12,2952.5 8346.12,3552.12 ; 827.45,2369.02 436.52,2369.02 436.52,4195.57 3322.17,4195.57 3322.17,2369.02 2531.81,2369.02 ; 827.45,2369.02 1712.92,2369.02 ; 1712.92,2369.02 2531.81,2369.02 ; 6302.5,2952.5 8967.8,2952.5 8967.8,3552.12 6302.5,3552.12 6302.5,2952.5
  text "Layer" at 503.6,4109.95 h57.08
  text "Name" at 894.53,4109.95 h57.08
  text "Material" at 1780,4109.95 h57.08
  text "Cu Thickness" at 2598.89,4109.95 h57.08
  text "Cu + Plating" at 3400,4082.85 h150
  text "Top Overlay" at 894.53,3995.79 h57.08
  text "Top Solder" at 894.53,3881.63 h57.08
  text "Solder Resist" at 1780,3881.63 h57.08
  text "0.39mil" at 2598.89,3881.63 h57.08
  text "1" at 503.6,3767.47 h57.08
  text "Top Layer" at 894.53,3767.47 h57.08
  text "1.40mil" at 2598.89,3767.47 h57.08
  text "1 Oz + Plating" at 3400,3760.76 h150
  text "Dielectric 8" at 894.53,3653.32 h57.08
  text "PP-1080" at 1780,3653.32 h57.08
  text "4.72mil" at 2598.89,3653.32 h57.08
  text "2" at 503.6,3539.16 h57.08
  text "Mid-Layer 1" at 894.53,3539.16 h57.08
  text "1.40mil" at 2598.89,3539.16 h57.08
  text "1 Oz" at 3400,3506.9 h150
  text "Symbol" at 6374.45,3468.17 h72
  text "Count" at 6632,3468.17 h72
  text "Hole Size" at 6906.19,3468.17 h72
  text "Plated" at 7445.09,3468.17 h72
  text "Hole Type" at 7670.72,3468.17 h72
  text "Hole Length" at 8001.59,3468.17 h72
  text "Routed Path Length" at 8382.09,3468.17 h72
  text "Dielectric 14" at 894.53,3425 h57.08
  text "Core" at 1780,3425 h57.08
  text "19.69mil" at 2598.89,3425 h57.08
  text "457" at 6632,3348.25 h60
  text "16.00mil (0.406mm)" at 6906.19,3348.25 h60
  text "PTH" at 7445.09,3348.25 h60
  text "Round" at 7670.72,3348.25 h60
  text "-" at 8001.59,3348.25 h60
  text "-" at 8382.09,3348.25 h60
  text "3" at 503.6,3310.84 h57.08
  text "Mid-Layer 2" at 894.53,3310.84 h57.08
  text "1.40mil" at 2598.89,3310.84 h57.08
  text "1 Oz" at 3400,3286.9 h150
  text "2" at 6632,3228.32 h60
  text "47.24mil (1.200mm)" at 6906.19,3228.32 h60
  text "PTH" at 7445.09,3228.32 h60
  text "Round" at 7670.72,3228.32 h60
  text "-" at 8001.59,3228.32 h60
  text "-" at 8382.09,3228.32 h60
  text "Dielectric 9" at 894.53,3196.68 h57.08
  text "PP-2116" at 1780,3196.68 h57.08
  text "4.72mil" at 2598.89,3196.68 h57.08
  text "4" at 6632,3108.4 h60
  text "125.98mil (3.200mm)" at 6906.19,3108.4 h60
  text "NPTH" at 7445.09,3108.4 h60
  text "Round" at 7670.72,3108.4 h60
  text "-" at 8001.59,3108.4 h60
  text "-" at 8382.09,3108.4 h60
  text "4" at 503.6,3082.52 h57.08
  text "Mid-Layer 3" at 894.53,3082.52 h57.08
  text "1.40mil" at 2598.89,3082.52 h57.08
  text "1 Oz" at 3400,3051.9 h150
  text "463 Total" at 6632,2988.47 h60
  text "Dielectric 13" at 894.53,2968.36 h57.08
  text "Core" at 1780,2968.36 h57.08
  text "19.69mil" at 2598.89,2968.36 h57.08
  text "5" at 503.6,2854.2 h57.08
  text "Mid-Layer 4" at 894.53,2854.2 h57.08
  text "1.40mil" at 2598.89,2854.2 h57.08
  text "1 Oz" at 3400,2836.9 h150
  text "Dielectric 11" at 894.53,2740.04 h57.08
  text "PP-1080" at 1780,2740.04 h57.08
  text "4.72mil" at 2598.89,2740.04 h57.08
  text "6" at 503.6,2625.88 h57.08
  text "Bottom Layer" at 894.53,2625.88 h57.08
  text "1.40mil" at 2598.89,2625.88 h57.08
  text "1 Oz + Plating" at 3400,2605.76 h150
  text "Bottom Solder" at 894.53,2511.72 h57.08
  text "Solder Resist" at 1780,2511.72 h57.08
  text "0.39mil" at 2598.89,2511.72 h57.08
  text "Bottom Overlay" at 894.53,2397.56 h57.08
  text "NOTES: UNLESS OTHERWISE SPECIFIED /  / 1.  THROUGH HOLES ARE PLATED THROUGH. /  /      EXCEPTIONS WILL BE NOTED IN DRILL CHART \"NOTE\". /  / 2.  MATERIAL: BASE MATERIAL LAMINATED EPOXY /  /      UL APPROVED MANUFACTURED SOURCE FOR FR4. /  / 3.  SOLDER PLATE WILL BE RoHS COMPLIANT. /  / 4.  SOLDER MASK LPI (LIQUID PHOTO IMAGEABLE) BOTH SIDES. COLOR GREEN. /  /       SOLDER MASK (REGISTRATION) -0/+0.003 /  / 5.  SILKSCREEN TOP SIDE. COLOR WHITE.(MIN.WIDTH 0.005\" MAX.WIDTH 0.010\") /  / 6.  FINISH TO BE HASL (Lead Free). /  / 7.  BOARD DIMENTION +/- 0.005\" /  / 8.  DRILL TOLERANCE+/-0.003\" /  / 9.  TRACE WIDTH UNDER 0.010\" +/- 0.002\" /  /        TRACE WIDTH OVER 0.011\" +/- 0.005\" /  / 10.  TRACE SPACE +/- 0.003\" /  / 11.  SLOTS WIDTH & LENGHTH +/- 0.005\" /  / 12.  MATERIAL FR4 COPPER 1oz THICKNESS 0.062\"" at 6240,-795 h60

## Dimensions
-130,-140 to 5500,-140 on Dimension
-130,2058.54 to -130,-140 on Dimension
